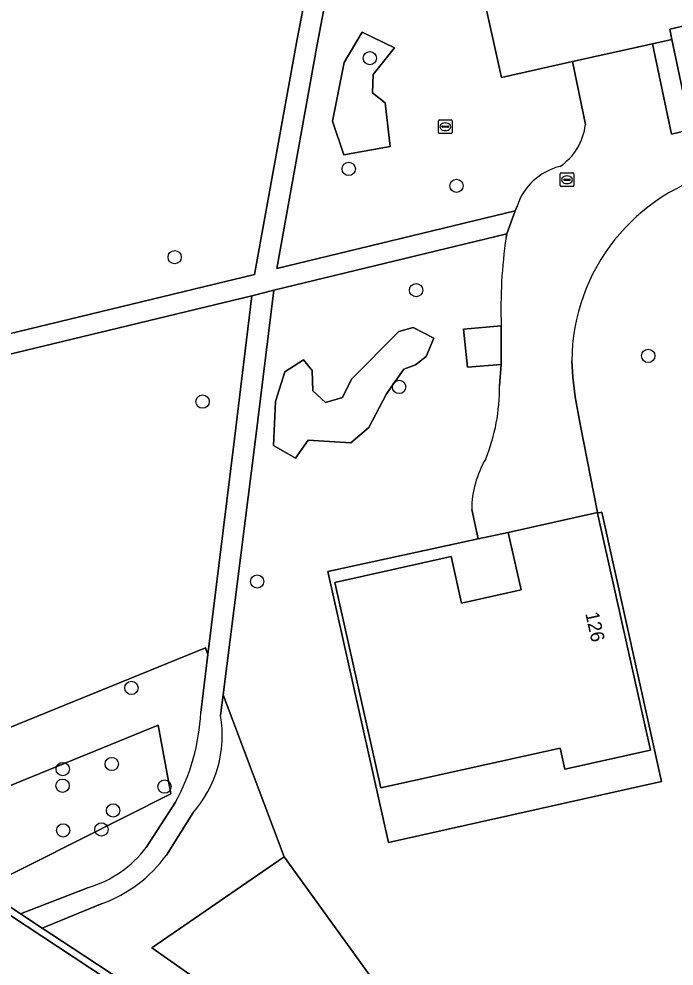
# Model space of a CAD drawing. Extents: x 156661 to 157576, y 383570 to 384425.
# Drawn here: x 156710.1 to 156758.2, y 383871.9 to 383941.5 of the extents above; entities that cross this region are included whole.
import ezdxf

# ---------------------------------------------------------------- set-up
doc = ezdxf.new("R2010")
doc.units = 0
for name, color, linetype in [('IMGEO_Boom', 7, 'Continuous'), ('IMGEO_Erf', 7, 'Continuous'), ('IMGEO_Groenvoorziening', 7, 'Continuous'), ('IMGEO_Kolk', 7, 'Continuous'), ('IMGEO_Pand', 7, 'Continuous'), ('IMGEO_Pand_nummerreeks', 7, 'Continuous'), ('IMGEO_Parkeervlak_halfverhard', 7, 'Continuous'), ('IMGEO_Rijbaan_lokaal_gesloten', 7, 'Continuous'), ('IMGEO_Rijbaan_lokaal_halfverhard', 7, 'Continuous'), ('IMGEO_Rijbaan_lokaal_open', 7, 'Continuous'), ('IMGEO_Rioolput', 7, 'Continuous'), ('IMGEO_Voetpad_open', 7, 'Continuous')]:
    doc.layers.add(name, color=color, linetype=linetype)

msp = doc.modelspace()

# ---------------------------------------------------------------- linework, layer by layer
at = {"layer": 'IMGEO_Boom'}
for centre in [(156735.871, 383938.637), (156734.316, 383930.494), (156742.242, 383929.251), (156721.523, 383924.009), (156739.269, 383921.583), (156756.336, 383916.75), (156738.021, 383914.466), (156723.575, 383913.387), (156727.587, 383900.168), (156718.346, 383892.342), (156713.295, 383886.376), (156716.896, 383886.751), (156713.28, 383885.156), (156720.774, 383885.087), (156716.997, 383883.339), (156713.324, 383881.871), (156716.135, 383881.94)]:
    msp.add_circle(centre, 0.489, dxfattribs=at)
at = {"layer": 'IMGEO_Erf'}
msp.add_lwpolyline([(156752.619, 383905.191), (156756.512, 383887.771), (156750.204, 383886.361), (156749.857, 383887.913), (156736.675, 383885.007), (156733.29, 383900.098), (156741.854, 383901.994), (156742.617, 383898.58), (156746.995, 383899.556), (156746.051, 383903.778), (156743.823, 383903.296), (156732.775, 383900.907), (156737.239, 383880.975), (156757.315, 383885.458), (156752.917, 383905.251)], close=True, dxfattribs=at)
at = {"layer": 'IMGEO_Groenvoorziening'}
for points in [[(156750.5, 384004.357), (156726.363, 383999.343), (156718.784, 383978.494), (156695.763, 383915.089), (156727.382, 383922.744), (156730.538, 383940.037), (156732.341, 383949.386), (156735.763, 383966.324)], [(156737.201, 383965.983), (156733.811, 383949.232), (156731.99, 383939.651), (156729.033, 383923.186), (156746.567, 383927.406), (156746.695, 383927.753)], [(156751.719, 383933.758), (156750.78, 383938.387), (156745.551, 383937.219), (156741.236, 383956.679), (156746.086, 383957.762), (156760.64, 383960.974), (156761.956, 383955.261), (156762.554, 383952.572), (156762.026, 383952.455), (156764.312, 383942.195), (156759.416, 383941.099), (156760.97, 383934.592)], [(156745.888, 383925.461), (156745.94, 383925.711), (156728.818, 383921.585), (156727.433, 383910.438), (156725.091, 383891.83), (156729.567, 383879.935), (156738.568, 383867.47)], [(156745.402, 383914.549), (156745.523, 383916.12), (156743.059, 383915.928), (156742.753, 383918.725), (156745.528, 383918.969)], [(156750.718, 383916.393), (156750.786, 383915.179), (156750.973, 383913.741), (156751.327, 383911.726), (156752.611, 383905.227), (156752.619, 383905.191), (156752.917, 383905.251), (156757.315, 383885.458), (156737.239, 383880.975), (156732.775, 383900.907), (156743.823, 383903.296), (156743.358, 383905.45)], [(156723.972, 383894.805), (156723.792, 383895.282), (156703.732, 383887.135), (156705.282, 383883.469), (156720.319, 383889.614), (156721.247, 383884.56), (156707.702, 383877.745), (156707.907, 383877.258), (156710.197, 383875.747), (156715.177, 383877.678)], [(156723.445, 383890.539), (156723.972, 383894.805)], [(156716.183, 383876.493), (156711.792, 383874.695), (156713.985, 383873.248), (156727.234, 383864.506), (156728.814, 383866.945), (156719.836, 383873.239), (156729.567, 383879.935), (156725.091, 383891.83)], [(156725.091, 383891.83), (156724.9, 383890.313)], [(156719.43, 383880.619), (156721.587, 383883.935)], [(156722.851, 383883.138), (156720.913, 383880.052)]]:
    msp.add_lwpolyline(points, dxfattribs=at)
for points in [[(156733.951, 383931.529), (156737.354, 383932.139), (156736.992, 383935.362), (156736.075, 383936.092), (156736.105, 383937.441), (156737.677, 383939.393), (156735.306, 383940.538), (156733.977, 383938.306), (156733.123, 383933.996)], [(156733.951, 383931.529), (156733.123, 383933.996), (156733.977, 383938.306), (156735.306, 383940.538), (156737.677, 383939.393), (156736.105, 383937.441), (156736.075, 383936.092), (156736.992, 383935.362), (156737.354, 383932.139)], [(156758.081, 383940.019), (156756.644, 383939.698), (156758.042, 383933.044), (156759.476, 383933.381)], [(156727.186, 383921.164), (156695.166, 383913.444), (156693.984, 383910.189), (156703.732, 383887.135), (156723.792, 383895.282), (156723.972, 383894.805), (156725.929, 383910.665)], [(156740.016, 383916.717), (156740.576, 383918.054), (156739.063, 383918.827), (156738.014, 383918.554), (156734.532, 383915.041), (156733.863, 383913.692), (156732.605, 383913.314), (156731.684, 383914.183), (156731.627, 383915.682), (156731.006, 383916.453), (156729.63, 383915.587), (156728.938, 383913.395), (156728.799, 383910.168), (156730.398, 383909.241), (156731.34, 383910.551), (156734.484, 383910.349), (156735.807, 383911.487), (156737.104, 383913.959), (156738.359, 383915.773), (156739.237, 383916.1)], [(156740.016, 383916.717), (156739.237, 383916.1), (156738.359, 383915.773), (156737.104, 383913.959), (156735.807, 383911.487), (156734.484, 383910.349), (156731.34, 383910.551), (156730.398, 383909.241), (156728.799, 383910.168), (156728.938, 383913.395), (156729.63, 383915.587), (156731.006, 383916.453), (156731.627, 383915.682), (156731.684, 383914.183), (156732.605, 383913.314), (156733.863, 383913.692), (156734.532, 383915.041), (156738.014, 383918.554), (156739.063, 383918.827), (156740.576, 383918.054)], [(156721.247, 383884.56), (156720.319, 383889.614), (156705.282, 383883.469), (156707.702, 383877.745)], [(156738.568, 383867.47), (156729.567, 383879.935), (156719.836, 383873.239), (156728.814, 383866.945), (156729.492, 383866.507), (156729.97, 383864.893), (156734.225, 383861.669), (156739.254, 383858.704), (156742.821, 383857.242), (156746.013, 383856.5), (156749.606, 383859.293), (156754.58, 383861.26), (156753.862, 383862.586), (156751.487, 383863.31), (156748.744, 383862.749), (156746.68, 383864.987), (156744.176, 383865.917), (156741.218, 383866.376)]]:
    msp.add_lwpolyline(points, close=True, dxfattribs=at)
for centre, radius, start, end in [((156747.519, 383934.205), 4.224, 303.15549, 353.92388), ((156750.876, 383926.402), 4.394, 103.78533, 162.08737), ((156765.181, 383916.263), 14.464, 103.41782, 179.48447), ((156781.68, 383920.22), 36.174, 171.66985, 181.98222), ((156731.335, 383914.398), 14.068, 338.2687, 0.61594), ((156750.723, 383905.407), 7.365, 149.10269, 179.66739), ((156707.845, 383891.364), 15.621, 331.6018, 356.97087), ((156716.401, 383888.86), 8.622, 318.42193, 9.70205), ((156712.9, 383885.516), 8.162, 286.19697, 323.13167), ((156712.758, 383885.968), 10.075, 289.87478, 324.04312)]:
    msp.add_arc(centre, radius, start, end, dxfattribs=at)
at = {"layer": 'IMGEO_Kolk'}
for p, q in [((156740.917, 383933.17), (156740.917, 383934.022)), ((156740.992, 383934.096), (156741.844, 383934.096)), ((156741.918, 383934.022), (156741.918, 383933.17)), ((156741.176, 383933.59), (156741.176, 383933.602)), ((156741.614, 383933.553), (156741.216, 383933.553)), ((156741.219, 383933.639), (156741.617, 383933.639)), ((156741.428, 383933.316), (156741.403, 383933.316)), ((156741.405, 383933.876), (156741.43, 383933.876)), ((156741.66, 383933.602), (156741.66, 383933.59)), ((156741.844, 383933.096), (156740.992, 383933.096))]:
    msp.add_line(p, q, dxfattribs=at)
for points in [[(156740.917, 383933.17), (156740.917, 383934.022)], [(156740.992, 383934.096), (156741.844, 383934.096)], [(156741.918, 383934.022), (156741.918, 383933.17)], [(156741.844, 383933.096), (156740.992, 383933.096)]]:
    msp.add_lwpolyline(points, dxfattribs=at)
for centre, radius, start, end in [((156740.994, 383934.02), 0.0765, 91.55205, 178.44795), ((156740.994, 383934.02), 0.0765, 91.55205, 178.44795), ((156741.842, 383934.02), 0.0765, 1.55205, 88.44795), ((156741.842, 383934.02), 0.0765, 1.55205, 88.44795), ((156741.216, 383933.599), 0.0403, 85.87752, 175.75265), ((156741.213, 383933.589), 0.0366, 178.93798, 274.71019), ((156741.617, 383933.596), 0.043, 264.86636, 352.45326), ((156741.621, 383933.601), 0.0386, 1.73085, 96.63898), ((156740.994, 383933.172), 0.0765, 181.55205, 268.44795), ((156740.994, 383933.172), 0.0765, 181.55205, 268.44795), ((156741.842, 383933.172), 0.0765, 271.55205, 358.44795), ((156741.842, 383933.172), 0.0765, 271.55205, 358.44795)]:
    msp.add_arc(centre, radius, start, end, dxfattribs=at)
for centre, major_axis, ratio, start_param, end_param in [((156741.404, 383933.596), (-0.387, 0.002), 0.722429, 4.712389, 7.853982), ((156741.429, 383933.596), (-0.39, 0.002), 0.717154, 1.570796, 4.712389)]:
    msp.add_ellipse(centre, major_axis=major_axis, ratio=ratio, start_param=start_param, end_param=end_param, dxfattribs=at)
at = {"layer": 'IMGEO_Pand'}
for points in [[(156762.026, 383952.455), (156762.554, 383952.572), (156761.956, 383955.261), (156756.462, 383954.041), (156757.728, 383948.318), (156748.639, 383946.279), (156746.086, 383957.762), (156741.236, 383956.679), (156745.551, 383937.219), (156750.78, 383938.387), (156756.644, 383939.698), (156758.081, 383940.019), (156757.925, 383940.765), (156759.416, 383941.099), (156764.312, 383942.195)], [(156752.619, 383905.191), (156752.611, 383905.227), (156746.051, 383903.778), (156746.995, 383899.556), (156742.617, 383898.58), (156741.854, 383901.994), (156733.29, 383900.098), (156736.675, 383885.007), (156749.857, 383887.913), (156750.204, 383886.361), (156756.512, 383887.771)]]:
    msp.add_lwpolyline(points, close=True, dxfattribs=at)
at = {"layer": 'IMGEO_Parkeervlak_halfverhard'}
msp.add_lwpolyline([(156745.528, 383918.969), (156742.753, 383918.725), (156743.059, 383915.928), (156745.523, 383916.12)], close=True, dxfattribs=at)
at = {"layer": 'IMGEO_Rijbaan_lokaal_gesloten'}
for points in [[(156760.97, 383934.592), (156759.416, 383941.099), (156757.925, 383940.765), (156758.081, 383940.019), (156759.476, 383933.381), (156758.042, 383933.044), (156756.644, 383939.698), (156750.78, 383938.387), (156751.719, 383933.758)], [(156746.695, 383927.753), (156746.567, 383927.406), (156745.94, 383925.711), (156745.888, 383925.461)], [(156745.528, 383918.969), (156745.523, 383916.12), (156745.402, 383914.549)], [(156743.358, 383905.45), (156743.823, 383903.296), (156746.051, 383903.778), (156752.611, 383905.227), (156751.327, 383911.726), (156750.973, 383913.741), (156750.786, 383915.179), (156750.718, 383916.393)]]:
    msp.add_lwpolyline(points, dxfattribs=at)
for centre, radius, start, end in [((156747.519, 383934.205), 4.224, 303.15549, 353.92388), ((156750.876, 383926.402), 4.394, 103.78533, 162.08737), ((156765.181, 383916.263), 14.464, 103.41782, 179.48447), ((156781.68, 383920.22), 36.174, 171.66985, 181.98222), ((156731.335, 383914.398), 14.068, 338.2687, 0.61594), ((156750.723, 383905.407), 7.365, 149.10269, 179.66739)]:
    msp.add_arc(centre, radius, start, end, dxfattribs=at)
at = {"layer": 'IMGEO_Rijbaan_lokaal_halfverhard'}
msp.add_lwpolyline([(156705.692, 383878.72), (156701.09, 383881.756), (156697.05, 383884.421), (156687.008, 383891.046), (156686.812, 383890.508), (156689.735, 383888.649), (156690.998, 383887.79), (156691.868, 383887.197), (156726.961, 383864.085), (156727.234, 383864.506), (156713.985, 383873.248), (156711.792, 383874.695), (156710.197, 383875.747), (156707.907, 383877.258), (156707.4, 383877.593)], close=True, dxfattribs=at)
at = {"layer": 'IMGEO_Rijbaan_lokaal_open'}
msp.add_lwpolyline([(156743.098, 383853.382), (156742.892, 383853.528), (156738.254, 383856.572), (156727.631, 383863.606), (156727.078, 383862.744), (156726.376, 383863.181), (156726.961, 383864.085), (156691.868, 383887.197), (156689.389, 383883.375), (156703.099, 383874.38), (156703.578, 383874.065), (156708.48, 383870.841), (156724.436, 383860.345), (156725.016, 383861.213), (156725.714, 383860.739), (156725.135, 383859.882), (156728.902, 383857.386), (156729.996, 383856.661), (156735.934, 383852.726), (156738.629, 383850.94), (156738.819, 383850.814)], dxfattribs=at)
at = {"layer": 'IMGEO_Rioolput'}
for p, q in [((156749.864, 383929.271), (156749.864, 383930.123)), ((156749.939, 383930.197), (156750.791, 383930.197)), ((156750.352, 383929.977), (156750.377, 383929.977)), ((156750.865, 383930.123), (156750.865, 383929.271)), ((156750.791, 383929.197), (156749.939, 383929.197)), ((156750.123, 383929.691), (156750.123, 383929.703)), ((156750.561, 383929.654), (156750.163, 383929.654)), ((156750.166, 383929.74), (156750.564, 383929.74)), ((156750.375, 383929.417), (156750.35, 383929.417)), ((156750.607, 383929.703), (156750.607, 383929.691))]:
    msp.add_line(p, q, dxfattribs=at)
for points in [[(156749.864, 383929.271), (156749.864, 383930.123)], [(156749.939, 383930.197), (156750.791, 383930.197)], [(156750.865, 383930.123), (156750.865, 383929.271)], [(156750.791, 383929.197), (156749.939, 383929.197)]]:
    msp.add_lwpolyline(points, dxfattribs=at)
for centre, radius, start, end in [((156749.941, 383930.121), 0.0765, 91.55205, 178.44795), ((156749.941, 383930.121), 0.0765, 91.55205, 178.44795), ((156750.789, 383930.121), 0.0765, 1.55205, 88.44795), ((156750.789, 383930.121), 0.0765, 1.55205, 88.44795), ((156749.941, 383929.273), 0.0765, 181.55205, 268.44795), ((156749.941, 383929.273), 0.0765, 181.55205, 268.44795), ((156750.163, 383929.7), 0.0403, 85.87752, 175.75265), ((156750.16, 383929.69), 0.0366, 178.93798, 274.71019), ((156750.564, 383929.697), 0.043, 264.86636, 352.45326), ((156750.568, 383929.702), 0.0386, 1.73085, 96.63898), ((156750.789, 383929.273), 0.0765, 271.55205, 358.44795), ((156750.789, 383929.273), 0.0765, 271.55205, 358.44795)]:
    msp.add_arc(centre, radius, start, end, dxfattribs=at)
for centre, major_axis, ratio, start_param, end_param in [((156750.351, 383929.697), (-0.387, 0.002), 0.722429, 4.712389, 7.853982), ((156750.376, 383929.697), (-0.39, 0.002), 0.717154, 1.570796, 4.712389)]:
    msp.add_ellipse(centre, major_axis=major_axis, ratio=ratio, start_param=start_param, end_param=end_param, dxfattribs=at)
at = {"layer": 'IMGEO_Voetpad_open'}
for points in [[(156735.763, 383966.324), (156732.341, 383949.386), (156730.538, 383940.037), (156727.382, 383922.744), (156695.763, 383915.089), (156695.166, 383913.444), (156727.186, 383921.164), (156728.818, 383921.585), (156745.94, 383925.711), (156746.567, 383927.406), (156729.033, 383923.186), (156731.99, 383939.651), (156733.811, 383949.232), (156737.201, 383965.983)], [(156725.091, 383891.83), (156727.433, 383910.438), (156728.818, 383921.585), (156727.186, 383921.164), (156725.929, 383910.665), (156723.972, 383894.805), (156723.445, 383890.539)], [(156724.9, 383890.313), (156725.091, 383891.83)], [(156721.587, 383883.935), (156719.43, 383880.619)], [(156720.913, 383880.052), (156722.851, 383883.138)], [(156715.177, 383877.678), (156710.197, 383875.747), (156711.792, 383874.695), (156716.183, 383876.493)]]:
    msp.add_lwpolyline(points, dxfattribs=at)
for centre, radius, start, end in [((156707.845, 383891.364), 15.621, 331.6018, 356.97087), ((156716.401, 383888.86), 8.622, 318.42193, 9.70205), ((156712.9, 383885.516), 8.162, 286.19697, 323.13167), ((156712.758, 383885.968), 10.075, 289.87478, 324.04312)]:
    msp.add_arc(centre, radius, start, end, dxfattribs=at)

# ---------------------------------------------------------------- texts
at = {"layer": 'IMGEO_Pand_nummerreeks'}
msp.add_text('126', height=1, rotation=282.59913, dxfattribs=at).set_placement((156751.704, 383897.823))

doc.saveas('drawing.dxf')
